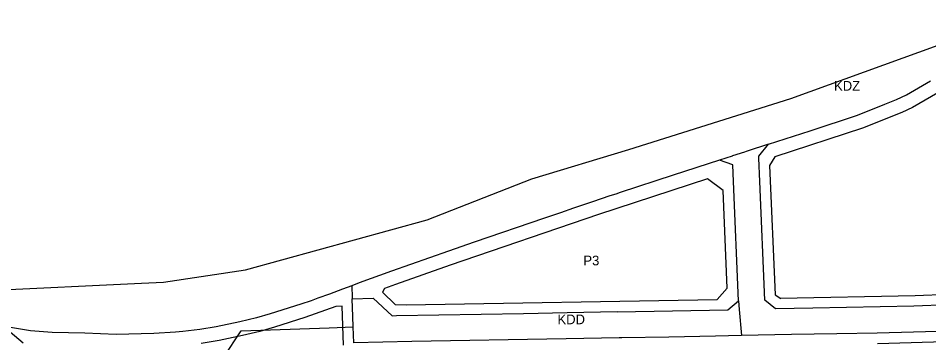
# Model space of a CAD drawing. Extents: x 7428103 to 7431580, y 5545880 to 5549002.
# Drawn here: x 7428821 to 7429340, y 5547123 to 5547308 of the extents above; entities that cross this region are included whole.
import ezdxf

# ---------------------------------------------------------------- set-up
doc = ezdxf.new("R2010")
doc.units = 0
for name, color, linetype in [('CZ_L_linie rozgraniczające tereny o różnym przeznaczeniu oraz różnych warunkach ich zabudowy i zagospodarowania', 7, 'Continuous'), ('CZ_L_maksymalne nieprzekraczalne linie zabudowy', 7, 'Continuous'), ('CZ_L_opisy_linie rozgraniczające tereny o różnym przeznaczeniu oraz różnych warunkach ich zabudowy i zagospodarowania', 7, 'Continuous'), ('CZYŻYNY - REJON ULICY GALICYJSKIEJ', 7, 'Continuous')]:
    doc.layers.add(name, color=color, linetype=linetype)

msp = doc.modelspace()

# ---------------------------------------------------------------- linework, layer by layer
at = {"layer": 'CZ_L_linie rozgraniczające tereny o różnym przeznaczeniu oraz różnych warunkach ich zabudowy i zagospodarowania'}
for p, q in [((7429327.56, 5547264.7), (7429341.29, 5547272.65)), ((7429315.35, 5547259.36), (7429321.92, 5547262.06)), ((7429321.92, 5547262.06), (7429327.56, 5547264.7)), ((7429299.72, 5547253.05), (7429315.35, 5547259.36)), ((7429272.6, 5547244.17), (7429299.72, 5547253.05)), ((7429248.99, 5547236.51), (7429272.6, 5547244.17)), ((7429248.99, 5547236.51), (7429243.25, 5547234.64)), ((7429243.34, 5547229.61), (7429248.99, 5547236.51)), ((7429113.92, 5547216.77), (7429169.2, 5547233.58)), ((7429228.18, 5547229.74), (7429220.98, 5547227.4)), ((7429228.35, 5547229.8), (7429228.18, 5547229.74)), ((7429235.22, 5547232.03), (7429228.35, 5547229.8)), ((7429236.15, 5547232.33), (7429235.22, 5547232.03)), ((7429242.37, 5547234.36), (7429236.15, 5547232.33)), ((7429243.13, 5547234.6), (7429242.37, 5547234.36)), ((7429243.25, 5547234.64), (7429243.13, 5547234.6)), ((7429243.38, 5547228.52), (7429243.34, 5547229.61)), ((7429220.98, 5547227.4), (7429194.56, 5547218.81)), ((7429228.55, 5547224.8), (7429220.98, 5547227.4)), ((7429228.95, 5547215.29), (7429228.55, 5547224.8)), ((7429243.93, 5547215.27), (7429243.38, 5547228.52)), ((7429054.16, 5547193.29), (7429113.92, 5547216.77)), ((7429194.56, 5547218.81), (7429164.27, 5547208.88)), ((7429231.75, 5547147.15), (7429228.95, 5547215.29)), ((7429246.74, 5547147.43), (7429243.93, 5547215.27)), ((7429164.27, 5547208.88), (7429161.8, 5547208.07)), ((7429148.58, 5547203.66), (7429137.61, 5547199.91)), ((7429158.43, 5547206.95), (7429148.58, 5547203.66)), ((7429161.8, 5547208.07), (7429158.43, 5547206.95)), ((7429137.61, 5547199.91), (7429130.34, 5547197.42)), ((7429121.21, 5547194.29), (7429081.1, 5547180.55)), ((7429130.34, 5547197.42), (7429121.21, 5547194.29)), ((7429081.1, 5547180.55), (7429066.41, 5547175.5)), ((7429066.41, 5547175.5), (7429033.84, 5547164.13)), ((7429033.84, 5547164.13), (7429015.51, 5547157.29)), ((7428891.33, 5547157.25), (7428903.88, 5547157.76)), ((7429015.51, 5547157.29), (7429011.21, 5547155.68)), ((7429005.98, 5547153.73), (7428998.58, 5547150.97)), ((7429011.21, 5547155.68), (7429005.98, 5547153.73)), ((7429011.21, 5547155.68), (7429011.46, 5547148.89)), ((7428987.98, 5547147.1), (7428982.2, 5547145.26)), ((7428991.91, 5547148.54), (7428987.98, 5547147.1)), ((7428998.58, 5547150.97), (7428991.91, 5547148.54)), ((7429011.46, 5547148.89), (7429011.49, 5547148.19)), ((7429011.49, 5547148.19), (7429023.48, 5547148.64)), ((7429011.86, 5547138.2), (7429011.49, 5547148.19)), ((7429023.48, 5547148.64), (7429034.29, 5547138.6)), ((7429225.71, 5547142.04), (7429231.75, 5547147.15)), ((7429231.75, 5547147.15), (7429232.19, 5547142.16)), ((7429252.97, 5547142.55), (7429246.74, 5547147.43)), ((7428982.2, 5547145.26), (7428964.74, 5547139.68)), ((7429162.61, 5547140.86), (7429225.71, 5547142.04)), ((7429232.19, 5547142.16), (7429233.5, 5547127.25)), ((7429274.15, 5547142.94), (7429252.97, 5547142.55)), ((7429331.73, 5547144.02), (7429274.15, 5547142.94)), ((7429351.35, 5547144.79), (7429331.73, 5547144.02)), ((7428956.98, 5547137.37), (7428947.3, 5547135.11)), ((7428964.74, 5547139.68), (7428956.98, 5547137.37)), ((7429012.08, 5547132.28), (7429011.86, 5547138.2)), ((7429034.29, 5547138.6), (7429036.78, 5547138.65)), ((7429036.78, 5547138.65), (7429109.22, 5547139.96)), ((7429109.22, 5547139.96), (7429134.17, 5547140.41)), ((7429134.17, 5547140.41), (7429143.54, 5547140.58)), ((7429143.54, 5547140.58), (7429162.55, 5547140.92)), ((7429162.55, 5547140.92), (7429162.61, 5547140.86)), ((7428812.73, 5547132.54), (7428823.86, 5547123.08)), ((7428827.96, 5547129.92), (7428814.29, 5547132.24)), ((7428933.97, 5547132.32), (7428924.48, 5547130.66)), ((7428947.3, 5547135.11), (7428933.97, 5547132.32)), ((7428948.07, 5547129.89), (7428998.31, 5547131.77)), ((7428998.31, 5547131.77), (7429012.08, 5547132.28)), ((7429012.42, 5547123.2), (7429012.08, 5547132.28)), ((7428840.36, 5547129.06), (7428827.96, 5547129.92)), ((7428858.99, 5547128.56), (7428840.36, 5547129.06)), ((7428876.94, 5547127.88), (7428858.99, 5547128.56)), ((7428898.35, 5547128.54), (7428876.94, 5547127.88)), ((7428910.64, 5547129.14), (7428898.35, 5547128.54)), ((7428914.87, 5547129.61), (7428910.64, 5547129.14)), ((7428924.48, 5547130.66), (7428914.87, 5547129.61)), ((7428938.04, 5547114.8), (7428948.07, 5547129.89)), ((7429163.75, 5547125.95), (7429133.5, 5547125.4)), ((7429165.19, 5547125.91), (7429163.75, 5547125.95)), ((7429192.1, 5547126.43), (7429165.19, 5547125.91)), ((7429218.6, 5547126.95), (7429192.1, 5547126.43)), ((7429233.5, 5547127.25), (7429218.6, 5547126.95)), ((7429262.1, 5547127.82), (7429233.5, 5547127.25)), ((7429287.85, 5547128.33), (7429262.1, 5547127.82)), ((7429310.91, 5547128.6), (7429287.85, 5547128.33)), ((7429355.44, 5547129.96), (7429310.91, 5547128.6)), ((7429045.45, 5547123.8), (7429012.42, 5547123.2)), ((7429133.5, 5547125.4), (7429045.45, 5547123.8))]:
    msp.add_line(p, q, dxfattribs=at)
for points in [[(7429169.2, 5547233.58), (7429261.57, 5547262.53), (7429356.72, 5547297.08), (7429356.72, 5547302.84), (7429356.86, 5547308.44)], [(7428903.88, 5547157.76), (7428950.54, 5547164.84), (7429054.16, 5547193.29)], [(7428683.22, 5547152.69), (7428716.69, 5547157), (7428739.47, 5547157.94), (7428759.33, 5547156.24), (7428767.35, 5547152.83), (7428770.62, 5547151.44), (7428790.34, 5547152.39), (7428803.45, 5547153.02), (7428891.33, 5547157.25)]]:
    msp.add_lwpolyline(points, dxfattribs=at)
at = {"layer": 'CZ_L_maksymalne nieprzekraczalne linie zabudowy'}
for points in [[(7429345.53, 5547265.87), (7429330.95, 5547257.45), (7429324.96, 5547254.66), (7429302.58, 5547245.58), (7429252.6, 5547229.27), (7429249.45, 5547224.3), (7429252.62, 5547150.44), (7429255.88, 5547148.43)], [(7429219.68, 5547147.93), (7429225.38, 5547154.29), (7429223.03, 5547210.12), (7429214.12, 5547216.76), (7429152.02, 5547196.38), (7429067.43, 5547167.38), (7429036.17, 5547156.46), (7429029.81, 5547154.09), (7429028.7, 5547152.14), (7429036.04, 5547145.09), (7429042.18, 5547144.77), (7429219.68, 5547147.93)], [(7429255.65, 5547148.6), (7429332.53, 5547150.06), (7429370.96, 5547151.68)], [(7429006.54, 5547121.84), (7429005.69, 5547144.03), (7429002.22, 5547143.88), (7428984.38, 5547137.56), (7428967.14, 5547132.05), (7428958.88, 5547129.6), (7428948.95, 5547127.28), (7428935.6, 5547124.49), (7428925.35, 5547122.71)], [(7429355.68, 5547123.96), (7429311.09, 5547122.6)]]:
    msp.add_lwpolyline(points, dxfattribs=at)
at = {"layer": 'CZYŻYNY - REJON ULICY GALICYJSKIEJ'}
for p, q in [((7429113.92, 5547216.77), (7429169.2, 5547233.58)), ((7429054.16, 5547193.29), (7429113.92, 5547216.77)), ((7428891.33, 5547157.25), (7428903.88, 5547157.76))]:
    msp.add_line(p, q, dxfattribs=at)
for points in [[(7429169.2, 5547233.58), (7429261.57, 5547262.53), (7429356.72, 5547297.08), (7429356.72, 5547302.84), (7429356.86, 5547308.44)], [(7428903.88, 5547157.76), (7428950.54, 5547164.84), (7429054.16, 5547193.29)], [(7428683.22, 5547152.69), (7428716.69, 5547157), (7428739.47, 5547157.94), (7428759.33, 5547156.24), (7428767.35, 5547152.83), (7428770.62, 5547151.44), (7428790.34, 5547152.39), (7428803.45, 5547153.02), (7428891.33, 5547157.25)]]:
    msp.add_lwpolyline(points, dxfattribs=at)

# ---------------------------------------------------------------- texts
at = {"layer": 'CZ_L_opisy_linie rozgraniczające tereny o różnym przeznaczeniu oraz różnych warunkach ich zabudowy i zagospodarowania'}
for s, p in [('KDZ', (7429286.32, 5547267.06)), ('P3', (7429143.34, 5547167.34)), ('KDD', (7429128.58, 5547133.73))]:
    msp.add_text(s, height=5.549, dxfattribs=at).set_placement(p)

doc.saveas('drawing.dxf')
